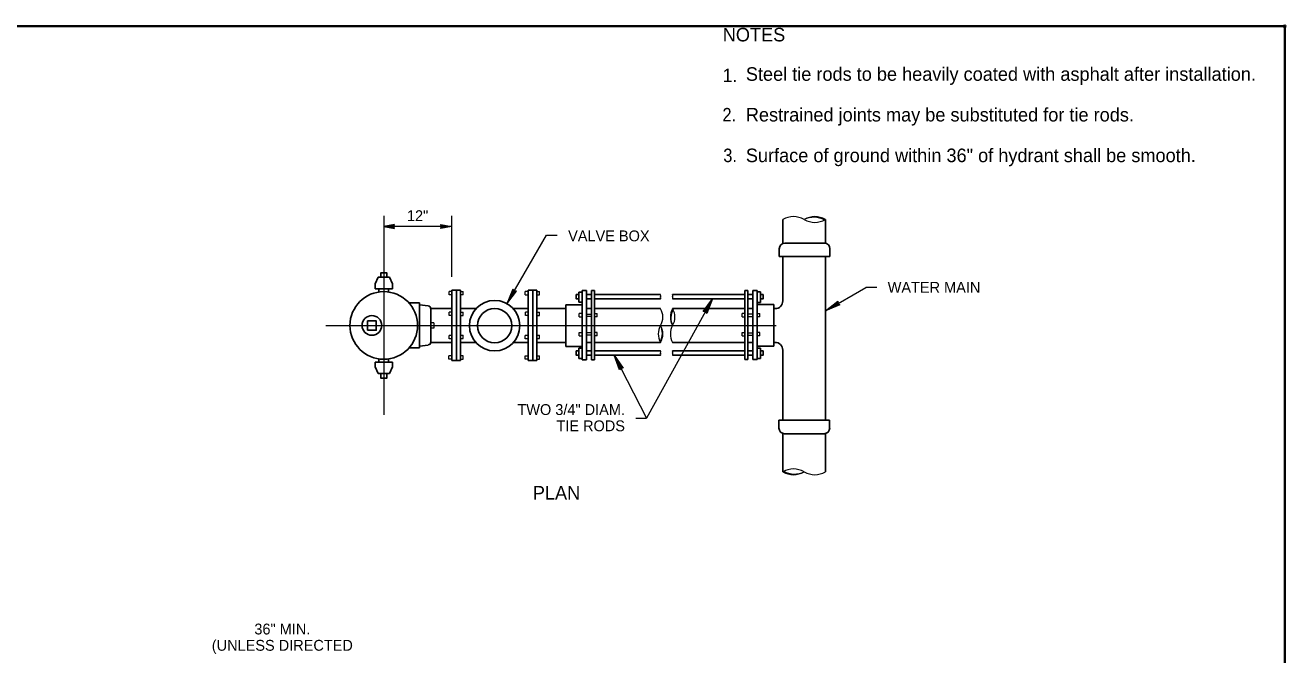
# Model space of a CAD drawing. Extents: x 99860 to 103153, y 99998 to 102077.
# Drawn here: x 101294 to 103153, y 101148 to 102077 of the extents above; entities that cross this region are included whole.
import ezdxf
from ezdxf.enums import TextEntityAlignment as Align

# ---------------------------------------------------------------- set-up
doc = ezdxf.new("R2010")
doc.units = 0
doc.header["$LTSCALE"] = 6.4
doc.header["$PDMODE"] = 32
doc.header["$PDSIZE"] = 3.2
for name, color, linetype, lineweight in [('1', 7, 'Continuous', 25), ('15', 7, 'Continuous', 13), ('18', 7, 'Continuous', 13), ('20', 7, 'Continuous', 13), ('6', 7, 'Continuous', 25)]:
    doc.layers.add(name, color=color, linetype=linetype, lineweight=lineweight)
doc.layers.add('60', color=7, linetype='Continuous')

msp = doc.modelspace()

# ---------------------------------------------------------------- hatches: boundary and pattern name
at = {"layer": '15'}
for points in [[(101822.327, 101780.136), (101838.052, 101777.052), (101837.324, 101780.136), (101838.052, 101783.22)], [(101922.077, 101780.136), (101906.352, 101777.052), (101907.08, 101780.136), (101906.352, 101783.22)], [(102003.998, 101666.325), (102017.997, 101684.603), (102014.883, 101685.179), (102012.827, 101687.588)], [(102307.008, 101673.279), (102298.587, 101651.85), (102296.485, 101654.218), (102293.361, 101654.736)], [(102473.802, 101655.95), (102492.08, 101669.949), (102492.656, 101666.835), (102495.065, 101664.779)], [(102162.202, 101590.354), (102175.31, 101571.426), (102172.173, 101570.998), (102170.003, 101568.692)]]:
    msp.add_hatch(color=256, dxfattribs=at).paths.add_polyline_path(points)

# ---------------------------------------------------------------- linework, layer by layer
at = {"layer": '1'}
for p, q in [((102397.664, 101658.991), (102399.452, 101658.991)), ((102397.664, 101609.254), (102399.452, 101609.254))]:
    msp.add_line(p, q, dxfattribs=at)
at = {"layer": '1', "lineweight": 35}
msp.add_lwpolyline([(99862, 99999.5), (103151, 99999.5), (103151, 102075.5), (99862, 102075.5)], close=True, dxfattribs=at)
at = {"layer": '15'}
for p, q in [((101822.327, 101796.136), (101822.327, 101502.38)), ((101922.077, 101796.136), (101922.077, 101706.079)), ((101922.077, 101780.136), (101822.327, 101780.136)), ((102003.998, 101666.325), (102062.253, 101767.226)), ((102062.253, 101767.226), (102078.253, 101767.226)), ((102307.008, 101673.279), (102209.999, 101497.568)), ((102473.802, 101655.95), (102533.487, 101690.41)), ((102549.487, 101690.41), (102533.487, 101690.41)), ((101737.117, 101634.268), (102401.069, 101634.268)), ((102162.202, 101590.354), (102209.999, 101497.568)), ((102193.999, 101497.568), (102209.999, 101497.568))]:
    msp.add_line(p, q, dxfattribs=at)
for points in [[(101822.327, 101780.136), (101838.052, 101777.052), (101837.324, 101780.136), (101838.052, 101783.22)], [(101922.077, 101780.136), (101906.352, 101777.052), (101907.08, 101780.136), (101906.352, 101783.22)], [(102003.998, 101666.325), (102017.997, 101684.603), (102014.883, 101685.179), (102012.827, 101687.588)], [(102307.008, 101673.279), (102298.587, 101651.85), (102296.485, 101654.218), (102293.361, 101654.736)], [(102473.802, 101655.95), (102492.08, 101669.949), (102492.656, 101666.835), (102495.065, 101664.779)], [(102162.202, 101590.354), (102175.31, 101571.426), (102172.173, 101570.998), (102170.003, 101568.692)]]:
    msp.add_lwpolyline(points, close=True, dxfattribs=at)
at = {"layer": '18', "lineweight": 25}
for p, q in [((101809.552, 101695.441), (101814.089, 101705.316)), ((101809.552, 101688.291), (101809.552, 101695.441)), ((101830.589, 101705.316), (101814.089, 101705.316)), ((101835.089, 101688.291), (101809.552, 101688.291)), ((101815.164, 101683.454), (101815.164, 101687.704)), ((101829.514, 101683.454), (101829.514, 101687.704)), ((101922.852, 101582.404), (101922.852, 101686.129)), ((101922.852, 101686.129), (101935.339, 101686.129)), ((101929.477, 101582.404), (101929.477, 101686.129)), ((101935.339, 101582.404), (101935.339, 101686.129)), ((102035.377, 101686.129), (102047.864, 101686.129)), ((102035.377, 101582.404), (102035.377, 101686.129)), ((102042.002, 101582.404), (102042.002, 101686.129)), ((102047.864, 101582.404), (102047.864, 101686.129)), ((102109.877, 101668.591), (102109.877, 101683.516)), ((102109.877, 101683.516), (102114.777, 101683.516)), ((102114.777, 101583.666), (102114.777, 101685.541)), ((102114.777, 101685.541), (102121.152, 101685.541)), ((102121.152, 101583.666), (102121.152, 101685.541)), ((102121.152, 101679.654), (102128.614, 101679.654)), ((102128.614, 101673.279), (102121.152, 101673.279)), ((102128.614, 101583.666), (102128.614, 101685.541)), ((102128.614, 101685.541), (102133.127, 101685.541)), ((102133.127, 101583.666), (102133.127, 101685.541)), ((102230.544, 101679.654), (102133.127, 101679.654)), ((102230.544, 101673.279), (102133.127, 101673.279)), ((102248.334, 101679.654), (102354.777, 101679.654)), ((102248.355, 101673.279), (102354.777, 101673.279)), ((102354.777, 101584.154), (102354.777, 101685.541)), ((102359.277, 101685.541), (102354.777, 101685.541)), ((102359.277, 101584.154), (102359.277, 101685.541)), ((102366.739, 101679.654), (102359.277, 101679.654)), ((102359.277, 101673.279), (102366.739, 101673.279)), ((102366.739, 101584.154), (102366.739, 101685.541)), ((102373.127, 101685.541), (102366.739, 101685.541)), ((102373.127, 101584.154), (102373.127, 101685.541)), ((102373.127, 101683.729), (102377.864, 101683.729)), ((102377.864, 101668.254), (102377.864, 101683.729)), ((101859.539, 101667.504), (101875.027, 101667.504)), ((101875.027, 101667.504), (101875.027, 101601.029)), ((101875.027, 101664.854), (101888.039, 101663.004)), ((101891.489, 101658.991), (101891.489, 101609.541)), ((101891.489, 101658.991), (101922.852, 101658.991)), ((101935.339, 101658.991), (101958.339, 101658.991)), ((102013.264, 101658.991), (102035.127, 101658.991)), ((102047.639, 101658.991), (102090.814, 101658.991)), ((102090.814, 101664.729), (102114.777, 101664.729)), ((102090.814, 101602.966), (102090.814, 101664.729)), ((102109.877, 101668.591), (102114.777, 101668.591)), ((102373.127, 101668.254), (102377.864, 101668.254)), ((101859.539, 101601.029), (101875.027, 101601.029)), ((101875.027, 101603.429), (101888.039, 101605.279)), ((101891.489, 101609.254), (101922.852, 101609.254)), ((101935.339, 101609.254), (101957.939, 101609.254)), ((102013.664, 101609.254), (102035.127, 101609.254)), ((102047.639, 101609.254), (102090.814, 101609.254)), ((102090.814, 101602.966), (102114.777, 101602.966)), ((102109.964, 101585.704), (102109.964, 101600.629)), ((102109.964, 101600.629), (102114.777, 101600.629)), ((102377.902, 101600.629), (102373.127, 101600.629)), ((102377.902, 101585.704), (102377.902, 101600.629)), ((101809.552, 101580.266), (101809.552, 101573.091)), ((101835.089, 101580.266), (101809.552, 101580.266)), ((101815.164, 101584.804), (101815.164, 101580.554)), ((101829.514, 101584.804), (101829.514, 101580.554)), ((101835.089, 101580.266), (101835.089, 101573.091)), ((101935.339, 101582.404), (101922.852, 101582.404)), ((102047.864, 101582.404), (102035.377, 101582.404)), ((102109.964, 101585.704), (102114.777, 101585.704)), ((102114.777, 101583.666), (102121.152, 101583.666)), ((102121.152, 101596.741), (102128.614, 101596.741)), ((102128.614, 101590.354), (102121.152, 101590.354)), ((102128.614, 101583.666), (102133.127, 101583.666)), ((102230.565, 101596.741), (102133.127, 101596.741)), ((102230.565, 101590.354), (102133.127, 101590.354)), ((102248.355, 101596.741), (102354.777, 101596.741)), ((102248.355, 101590.354), (102354.777, 101590.354)), ((102359.277, 101584.154), (102354.777, 101584.154)), ((102366.739, 101596.741), (102359.277, 101596.741)), ((102359.277, 101590.354), (102366.739, 101590.354)), ((102373.127, 101584.154), (102366.739, 101584.154)), ((102377.902, 101585.704), (102373.127, 101585.704)), ((101809.552, 101573.091), (101814.089, 101563.254)), ((101830.589, 101563.254), (101814.089, 101563.254)), ((101835.089, 101573.091), (101830.589, 101563.254))]:
    msp.add_line(p, q, dxfattribs=at)
at = {"layer": '18'}
for p, q in [((101922.852, 101684.379), (101918.527, 101684.379)), ((101918.527, 101679.416), (101918.527, 101684.379)), ((101922.852, 101679.416), (101918.527, 101679.416)), ((101935.339, 101684.379), (101939.477, 101684.379)), ((101939.477, 101679.416), (101935.339, 101679.416)), ((101939.477, 101679.416), (101939.477, 101684.379)), ((102035.377, 101684.379), (102031.052, 101684.379)), ((102031.052, 101679.416), (102031.052, 101684.379)), ((102031.052, 101679.416), (102035.377, 101679.416)), ((102047.864, 101684.379), (102051.989, 101684.379)), ((102047.864, 101679.416), (102051.989, 101679.416)), ((102051.989, 101679.416), (102051.989, 101684.379)), ((101896.302, 101638.279), (101891.489, 101638.279)), ((101918.652, 101648.916), (101918.652, 101653.879)), ((101922.852, 101653.879), (101918.652, 101653.879)), ((101922.752, 101648.916), (101918.652, 101648.916)), ((101935.339, 101653.879), (101939.439, 101653.879)), ((101935.339, 101648.916), (101939.439, 101648.916)), ((101939.439, 101648.916), (101939.439, 101653.879)), ((102031.177, 101648.916), (102031.177, 101653.879)), ((102035.377, 101653.879), (102031.177, 101653.879)), ((102035.277, 101648.916), (102031.177, 101648.916)), ((102047.864, 101653.879), (102051.964, 101653.879)), ((102047.864, 101648.916), (102051.964, 101648.916)), ((102051.964, 101648.916), (102051.964, 101653.879)), ((102114.714, 101651.716), (102110.677, 101651.716)), ((102110.677, 101646.754), (102110.677, 101651.716)), ((102110.677, 101646.754), (102114.714, 101646.754)), ((102121.102, 101651.016), (102128.564, 101651.016)), ((102128.564, 101647.491), (102121.102, 101647.491)), ((102137.102, 101646.754), (102133.064, 101646.754)), ((102133.127, 101651.716), (102137.102, 101651.716)), ((102137.102, 101646.754), (102137.102, 101651.716)), ((102354.777, 101651.754), (102350.677, 101651.754)), ((102350.677, 101646.791), (102350.677, 101651.754)), ((102350.677, 101646.791), (102354.777, 101646.791)), ((102366.739, 101651.041), (102359.277, 101651.041)), ((102359.277, 101647.529), (102366.739, 101647.529)), ((102373.127, 101651.754), (102377.102, 101651.754)), ((102377.102, 101646.791), (102373.127, 101646.791)), ((102377.102, 101646.791), (102377.102, 101651.754)), ((101918.527, 101614.504), (101918.527, 101619.466)), ((101922.852, 101619.466), (101918.527, 101619.466)), ((101935.339, 101619.841), (101939.564, 101619.841)), ((101939.564, 101614.866), (101939.564, 101619.841)), ((102031.052, 101614.504), (102031.052, 101619.466)), ((102035.377, 101619.466), (102031.052, 101619.466)), ((102047.864, 101619.841), (102052.089, 101619.841)), ((102052.089, 101614.866), (102052.089, 101619.841)), ((102110.702, 101624.029), (102114.714, 101624.029)), ((102110.702, 101619.066), (102110.702, 101624.029)), ((102110.702, 101619.066), (102114.777, 101619.066)), ((102128.614, 101623.316), (102121.152, 101623.316)), ((102128.614, 101619.841), (102121.152, 101619.841)), ((102137.127, 101624.029), (102133.127, 101624.029)), ((102137.127, 101619.066), (102133.127, 101619.066)), ((102137.127, 101619.066), (102137.127, 101624.029)), ((102350.639, 101624.054), (102354.777, 101624.054)), ((102350.639, 101619.091), (102350.639, 101624.054)), ((102350.639, 101619.091), (102354.777, 101619.091)), ((102359.277, 101623.354), (102366.739, 101623.354)), ((102359.277, 101619.866), (102366.739, 101619.866)), ((102377.064, 101624.054), (102373.127, 101624.054)), ((102377.064, 101619.091), (102373.127, 101619.091)), ((102377.064, 101619.091), (102377.064, 101624.054)), ((101922.852, 101614.504), (101918.527, 101614.504)), ((101935.339, 101614.866), (101939.564, 101614.866)), ((102035.377, 101614.504), (102031.052, 101614.504)), ((102047.864, 101614.866), (102052.089, 101614.866)), ((101918.439, 101584.316), (101918.439, 101589.279)), ((101922.852, 101589.279), (101918.439, 101589.279)), ((101922.852, 101584.316), (101918.439, 101584.316)), ((101939.414, 101589.279), (101935.339, 101589.279)), ((101935.339, 101584.254), (101939.414, 101584.254)), ((101939.414, 101584.254), (101939.414, 101589.279)), ((102030.964, 101584.316), (102030.964, 101589.216)), ((102030.964, 101589.216), (102035.377, 101589.216)), ((102035.377, 101584.316), (102030.964, 101584.316)), ((102047.864, 101589.216), (102051.927, 101589.216)), ((102047.864, 101584.254), (102051.927, 101584.254)), ((102051.927, 101584.254), (102051.927, 101589.216))]:
    msp.add_line(p, q, dxfattribs=at)
at = {"layer": '18', "lineweight": 25}
for points in [[(101817.827, 101705.316), (101817.827, 101711.666), (101826.852, 101711.666), (101826.852, 101705.316)], [(101798.427, 101627.079), (101798.427, 101640.891), (101811.189, 101640.891), (101811.189, 101627.079)], [(101817.827, 101563.254), (101817.827, 101556.616), (101826.852, 101556.616), (101826.852, 101563.254)]]:
    msp.add_lwpolyline(points, close=True, dxfattribs=at)
for points in [[(101835.089, 101688.291), (101835.089, 101695.441), (101830.589, 101705.316)], [(102109.877, 101679.691), (102106.177, 101679.691), (102106.177, 101673.304), (102109.877, 101673.304)], [(102377.864, 101679.654), (102381.627, 101679.654), (102381.627, 101673.279), (102377.864, 101673.279)], [(102109.964, 101596.741), (102106.114, 101596.741), (102106.114, 101590.354), (102109.964, 101590.354)], [(102377.902, 101596.741), (102381.664, 101596.741), (102381.664, 101590.354), (102377.902, 101590.354)]]:
    msp.add_lwpolyline(points, dxfattribs=at)
at = {"layer": '18'}
msp.add_lwpolyline([(101896.302, 101638.279), (101896.302, 101630.016), (101891.489, 101630.016)], dxfattribs=at)
at = {"layer": '18', "lineweight": 25}
for centre, radius in [((101822.336, 101634.192), 49.868), ((101985.802, 101633.896), 37.185), ((101985.802, 101633.896), 25.361), ((101804.783, 101634.192), 14.468)]:
    msp.add_circle(centre, radius, dxfattribs=at)
at = {"layer": '18'}
for centre, radius, start, end in [((102233.304, 101674.873), 3.188, 150, 210), ((102227.783, 101678.06), 3.188, 330, 30), ((102227.783, 101674.873), 3.188, 330, 30), ((102251.116, 101678.06), 3.188, 150, 210), ((102251.116, 101674.873), 3.188, 150, 210), ((102245.595, 101678.06), 3.188, 330, 30), ((102233.331, 101591.951), 3.194, 150, 210), ((102227.799, 101595.144), 3.194, 330, 30), ((102227.799, 101591.951), 3.194, 330, 30), ((102251.121, 101595.144), 3.194, 150, 210), ((102251.121, 101591.951), 3.194, 150, 210), ((102245.589, 101595.144), 3.194, 330, 30)]:
    msp.add_arc(centre, radius, start, end, dxfattribs=at)
at = {"layer": '18', "lineweight": 25}
for centre, start, end in [((101887.433, 101658.87), 0, 81.50484), ((101887.433, 101609.515), 278.49516, 0)]:
    msp.add_arc(centre, 4.156, start, end, dxfattribs=at)
at = {"layer": '6'}
for p, q in [((102410.802, 101755.704), (102410.802, 101790.353)), ((102473.802, 101755.704), (102473.802, 101790.516)), ((102405.627, 101735.716), (102405.627, 101747.441)), ((102413.889, 101755.704), (102472.164, 101755.704)), ((102480.402, 101735.716), (102480.402, 101747.441)), ((102405.627, 101735.716), (102480.402, 101735.716)), ((102410.802, 101670.341), (102410.802, 101735.716)), ((102473.802, 101494.491), (102473.802, 101735.716)), ((102121.152, 101658.991), (102128.614, 101658.991)), ((102133.127, 101658.991), (102230.544, 101658.991)), ((102248.334, 101658.991), (102354.777, 101658.991)), ((102359.277, 101658.991), (102366.739, 101658.991)), ((102397.664, 101665.254), (102373.127, 101665.254)), ((102397.664, 101603.491), (102397.664, 101665.254)), ((102121.152, 101609.254), (102128.614, 101609.254)), ((102133.127, 101609.254), (102230.565, 101609.254)), ((102248.355, 101609.254), (102354.777, 101609.254)), ((102359.427, 101609.254), (102366.739, 101609.254)), ((102397.664, 101603.491), (102373.127, 101603.491)), ((102410.802, 101494.491), (102410.802, 101597.916)), ((102405.127, 101494.491), (102405.127, 101482.766)), ((102479.877, 101494.491), (102405.127, 101494.491)), ((102479.877, 101494.491), (102479.877, 101482.766)), ((102410.802, 101418.281), (102410.802, 101474.504)), ((102471.639, 101474.504), (102413.364, 101474.504)), ((102473.802, 101418.28), (102473.802, 101474.504))]:
    msp.add_line(p, q, dxfattribs=at)
at = {"layer": '6', "lineweight": 13}
for centre, radius, start, end in [((102426.552, 101763.236), 31.5, 60, 120), ((102456.388, 101762.13), 31.689, 60.18317, 116.39347), ((102458.052, 101763.236), 31.5, 60, 120), ((102458.052, 101817.796), 31.5, 240, 300), ((102209.045, 101646.529), 24.85, 330, 30), ((102269.876, 101646.529), 24.85, 150, 210), ((102270.748, 101645.217), 24.999, 150.18317, 206.39347), ((102226.835, 101646.529), 24.85, 330, 30), ((102252.086, 101621.679), 24.85, 150, 210), ((102208.172, 101622.991), 24.999, 330.18317, 26.39347), ((102209.045, 101621.679), 24.85, 330, 30), ((102269.876, 101621.679), 24.85, 150, 210), ((102426.552, 101391.001), 31.5, 60, 120), ((102426.552, 101445.56), 31.5, 240, 300), ((102428.215, 101446.666), 31.689, 240.18317, 296.39347), ((102458.052, 101445.56), 31.5, 240, 300)]:
    msp.add_arc(centre, radius, start, end, dxfattribs=at)
at = {"layer": '6'}
for centre, radius, start, end in [((102413.91, 101747.331), 8.311, 90, 180), ((102472.089, 101747.331), 8.311, 0, 90), ((102399.463, 101670.333), 11.348, 270, 0), ((102399.463, 101597.92), 11.348, 0, 90), ((102413.434, 101482.871), 8.311, 180, 270), ((102471.614, 101482.871), 8.311, 270, 0)]:
    msp.add_arc(centre, radius, start, end, dxfattribs=at)
at = {"layer": '60'}
msp.add_point((103151, 102075.5), dxfattribs=at)

# ---------------------------------------------------------------- texts
at = {"layer": '20'}
for s, height, p in [('NOTES', 20, (102322.268, 102053.186)), ('Steel tie rods to be heavily coated with asphalt after installation.', 20, (102356.31, 101995.096)), ('Restrained joints may be substituted for tie rods.', 20, (102356.31, 101935.096)), ('Surface of ground within 36" of hydrant shall be smooth.', 20, (102356.31, 101875.096)), ('VALVE BOX', 16, (102094.229, 101758.345)), ('WATER MAIN', 16, (102565.487, 101682.41))]:
    msp.add_text(s, height=height, dxfattribs=at).set_placement(p)
for s, width, p in [('1.', 0.95, (102322.268, 101993.186)), ('2.', 0.9, (102321.869, 101935.096)), ('3.', 0.9, (102323.066, 101875.096))]:
    msp.add_text(s, height=20, dxfattribs=dict(at, width=width)).set_placement(p)
for s, height, p in [('12"', 16, (101872.205, 101788.136)), ('PLAN', 20, (102077.054, 101377.369)), ('36" MIN.', 16, (101672.725, 101178.385)), ('(UNLESS DIRECTED', 16, (101672.724, 101154.385))]:
    msp.add_text(s, height=height, dxfattribs=at).set_placement(p, align=Align.CENTER)
for s, p in [('TWO 3/4" DIAM.', (102178.013, 101502.134)), ('TIE RODS', (102178.013, 101478.134))]:
    msp.add_text(s, height=16, dxfattribs=at).set_placement(p, align=Align.RIGHT)

doc.saveas('drawing.dxf')
